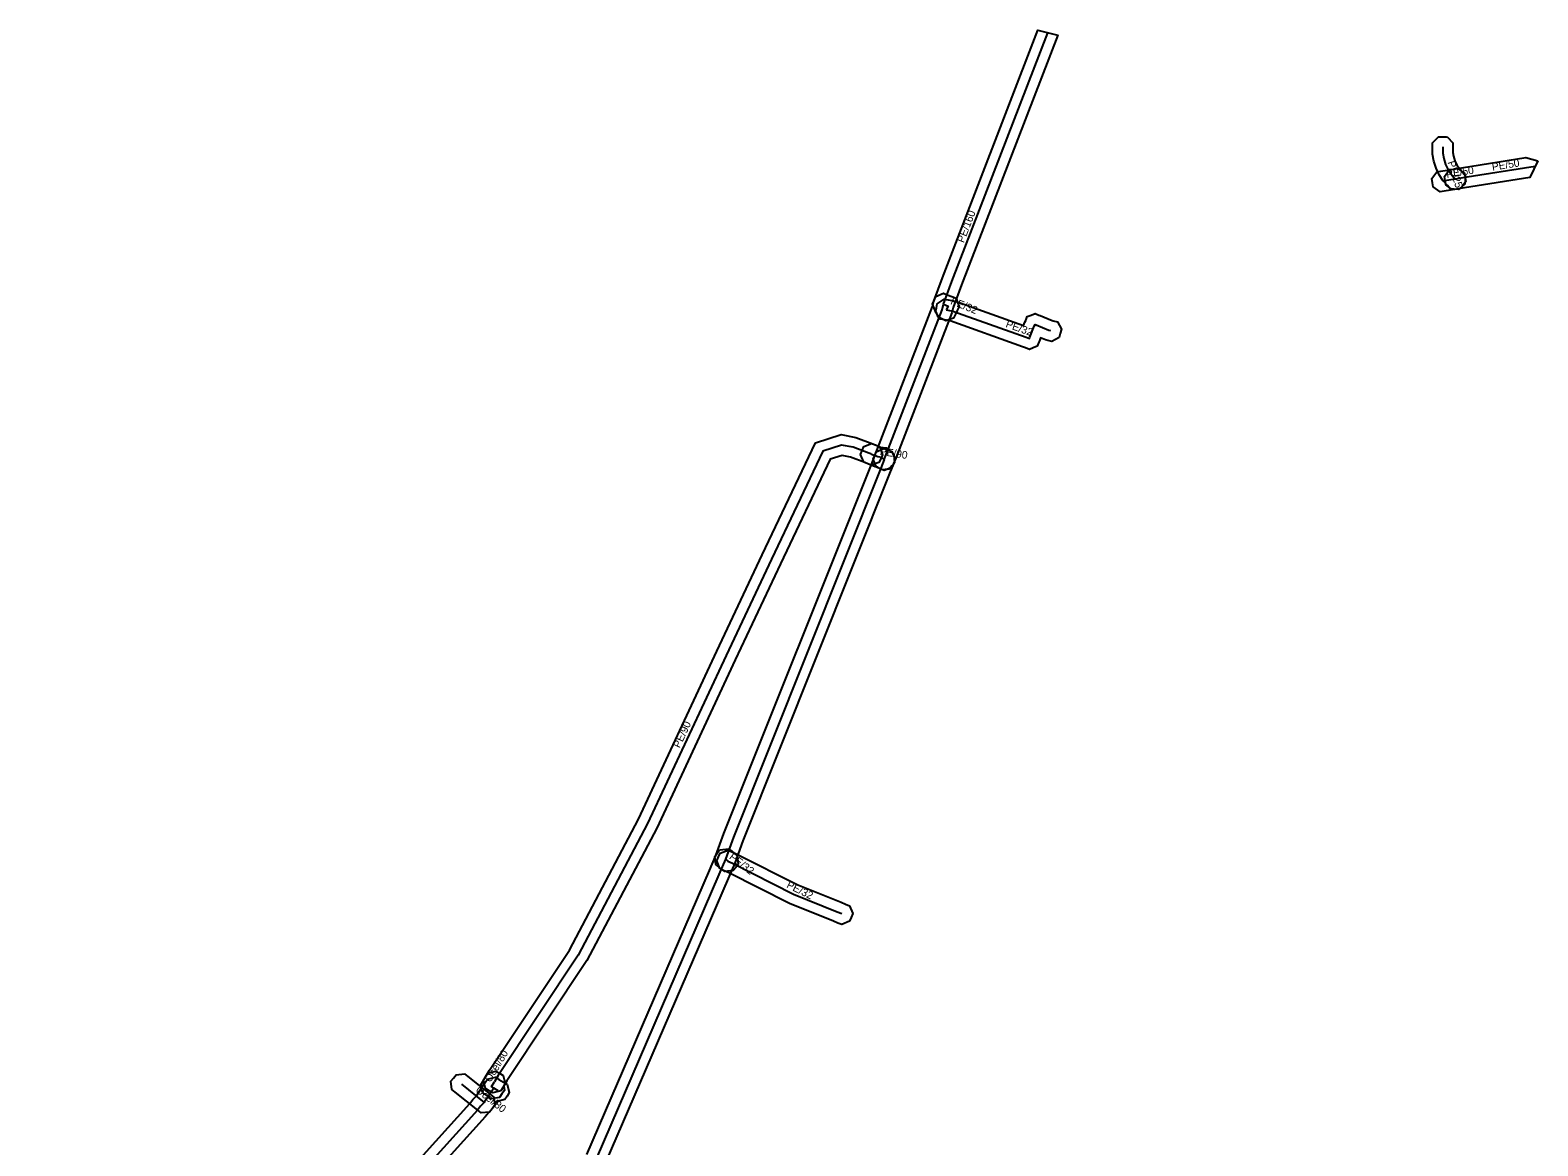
# Model space of a CAD drawing. Extents: x -843502 to -843208, y -997248 to -997028.
# Drawn here: x -843356.7 to -843208.1, y -997138.4 to -997028.5 of the extents above; entities that cross this region are included whole.
import ezdxf

# ---------------------------------------------------------------- set-up
doc = ezdxf.new("R2010")
doc.units = 0
for name, color, linetype in [('1', 7, 'Continuous'), ('24', 7, 'Continuous'), ('30', 7, 'Continuous')]:
    doc.layers.add(name, color=color, linetype=linetype)

msp = doc.modelspace()

# ---------------------------------------------------------------- linework, layer by layer
at = {"layer": '1'}
for points in [[(-843266.81, -997052.89), (-843257.39, -997028.49), (-843255.44, -997029), (-843264.93, -997053.59), (-843265.74, -997055.8), (-843265.89, -997056.34), (-843271.4, -997070.67), (-843271.62, -997071.17), (-843271.78, -997071.56), (-843272.55, -997071.86), (-843272.93, -997071.7), (-843273.31, -997071.54), (-843273.62, -997070.77), (-843273.46, -997070.39), (-843273.26, -997069.91), (-843267.79, -997055.72), (-843267.64, -997055.19)], [(-843217.19, -997038.99), (-843217.06, -997039.02), (-843216.51, -997039.58), (-843216.51, -997039.99), (-843216.51, -997040.54), (-843216.45, -997040.92), (-843216.31, -997041.35), (-843216.12, -997041.76), (-843215.9, -997042.09), (-843215.54, -997042.51), (-843215.27, -997042.83), (-843215.34, -997043.65), (-843215.65, -997043.92), (-843215.97, -997044.19), (-843216.79, -997044.12), (-843217.06, -997043.81), (-843217.5, -997043.29), (-843217.86, -997042.74), (-843218.17, -997042.09), (-843218.39, -997041.39), (-843218.51, -997040.7), (-843218.51, -997039.99), (-843218.51, -997039.58), (-843217.92, -997038.99), (-843217.51, -997038.99)], [(-843215.73, -997044.08), (-843216.14, -997044.15), (-843217.37, -997044.35), (-843217.78, -997044.41), (-843218.45, -997043.93), (-843218.52, -997043.52), (-843218.58, -997043.11), (-843218.1, -997042.44), (-843217.69, -997042.37), (-843216.46, -997042.17), (-843216.05, -997042.11), (-843215.38, -997042.59), (-843215.31, -997043), (-843215.25, -997043.41)], [(-843208.15, -997041.35), (-843208.94, -997043), (-843215.36, -997044.03), (-843216.15, -997044.15), (-843216.56, -997044.21), (-843217.22, -997043.72), (-843217.29, -997043.31), (-843217.35, -997042.9), (-843216.86, -997042.23), (-843216.45, -997042.17), (-843215.68, -997042.05), (-843209.34, -997041.04)], [(-843267.23, -997056.76), (-843267.39, -997056.29), (-843267.45, -997056.26), (-843267.77, -997055.5), (-843267.62, -997055.12), (-843267.46, -997054.73), (-843266.7, -997054.41), (-843266.32, -997054.56), (-843265.87, -997054.74), (-843265.46, -997054.9), (-843265.31, -997055.31), (-843265.15, -997055.72), (-843265.34, -997056.11), (-843265.52, -997056.48), (-843265.7, -997056.85), (-843266.48, -997057.12), (-843266.86, -997056.94)], [(-843265.52, -997055.19), (-843258.8, -997057.59), (-843258.68, -997057.27), (-843258.6, -997057.1), (-843258.45, -997056.71), (-843258.06, -997056.56), (-843257.68, -997056.4), (-843257.3, -997056.56), (-843257.18, -997056.61), (-843256, -997057.09), (-843255.88, -997057.13), (-843255.48, -997057.24), (-843255.08, -997057.96), (-843255.19, -997058.36), (-843255.3, -997058.76), (-843256.02, -997059.17), (-843256.42, -997059.05), (-843256.66, -997058.99), (-843257.13, -997058.79), (-843257.25, -997059.09), (-843257.31, -997059.24), (-843257.47, -997059.63), (-843257.85, -997059.79), (-843258.23, -997059.95), (-843258.62, -997059.8), (-843258.92, -997059.68), (-843266.04, -997057.13), (-843266.6, -997057.02), (-843267.01, -997056.95), (-843267.48, -997056.26), (-843267.4, -997055.86), (-843267.33, -997055.45), (-843266.64, -997054.98), (-843266.24, -997055.06)], [(-843273.84, -997071.36), (-843274.22, -997071.18), (-843274.31, -997071.14), (-843274.44, -997071.07), (-843275.86, -997070.55), (-843276.67, -997070.4), (-843277.85, -997070.77), (-843282.75, -997081.05), (-843287.21, -997090.52), (-843294.94, -997107.09), (-843301.83, -997120.13), (-843309.71, -997131.99), (-843310.08, -997132.61), (-843310.29, -997132.97), (-843311.09, -997133.18), (-843311.45, -997132.97), (-843311.8, -997132.76), (-843312.01, -997131.96), (-843311.8, -997131.6), (-843311.41, -997130.93), (-843303.55, -997119.11), (-843296.74, -997106.21), (-843289.03, -997089.67), (-843284.55, -997080.19), (-843279.29, -997069.13), (-843276.79, -997068.34), (-843275.32, -997068.61), (-843273.66, -997069.23), (-843273.44, -997069.33), (-843273.34, -997069.38), (-843272.97, -997069.56), (-843272.7, -997070.34), (-843272.88, -997070.72), (-843273.06, -997071.09)], [(-843272.86, -997071.82), (-843273.18, -997071.55), (-843273.19, -997071.54), (-843273.44, -997071.5), (-843274.16, -997071.21), (-843274.54, -997071.05), (-843274.86, -997070.28), (-843274.71, -997069.9), (-843274.55, -997069.52), (-843273.78, -997069.2), (-843273.4, -997069.35), (-843272.9, -997069.56), (-843272.35, -997069.64), (-843271.9, -997070.01), (-843271.58, -997070.28), (-843271.51, -997071.1), (-843271.77, -997071.42), (-843272.04, -997071.74)], [(-843287.89, -997109.13), (-843287.56, -997109.38), (-843287.33, -997109.56), (-843287.01, -997109.82), (-843286.91, -997110.64), (-843287.16, -997110.97), (-843287.42, -997111.29), (-843288.24, -997111.39), (-843288.57, -997111.14), (-843288.8, -997110.96), (-843289.12, -997110.7), (-843289.22, -997109.88), (-843288.97, -997109.55), (-843288.71, -997109.23)], [(-843287.91, -997109.27), (-843287.54, -997109.44), (-843287.06, -997109.66), (-843281.05, -997112.69), (-843276.78, -997114.41), (-843276.34, -997114.59), (-843275.96, -997114.75), (-843275.64, -997115.52), (-843275.79, -997115.9), (-843275.95, -997116.28), (-843276.71, -997116.6), (-843277.1, -997116.45), (-843277.54, -997116.27), (-843281.87, -997114.51), (-843287.92, -997111.46), (-843288.36, -997111.26), (-843288.74, -997111.09), (-843289.03, -997110.31), (-843288.86, -997109.94), (-843288.69, -997109.56)], [(-843313.88, -997131.3), (-843313.56, -997131.56), (-843311.32, -997133.34), (-843310.99, -997133.59), (-843310.9, -997134.42), (-843311.16, -997134.74), (-843311.42, -997135.07), (-843312.24, -997135.16), (-843312.56, -997134.9), (-843314.8, -997133.12), (-843315.13, -997132.86), (-843315.22, -997132.04), (-843314.96, -997131.72), (-843314.71, -997131.39)], [(-843309.87, -997132.27), (-843310.02, -997132.52), (-843309.95, -997132.95), (-843310.19, -997133.29), (-843310.43, -997133.63), (-843311.24, -997133.77), (-843311.58, -997133.52), (-843311.79, -997133.37), (-843312.11, -997133.15), (-843312.27, -997132.38), (-843312.07, -997132.05), (-843311.8, -997131.6), (-843311.58, -997131.24), (-843310.78, -997131.04), (-843310.43, -997131.25), (-843310.07, -997131.47)]]:
    msp.add_lwpolyline(points, close=True, dxfattribs=at)
for points in [[(-843301.82, -997139.24), (-843289.74, -997111.29), (-843289.11, -997109.8), (-843288.32, -997107.64), (-843273.8, -997071.29), (-843273.47, -997070.43), (-843273.33, -997070.04), (-843272.57, -997069.7), (-843272.19, -997069.85), (-843271.8, -997069.99), (-843271.46, -997070.75), (-843271.6, -997071.14), (-843271.94, -997072.01), (-843286.46, -997108.36), (-843287.25, -997110.54), (-843287.9, -997112.07), (-843300.02, -997140.1)], [(-843320.04, -997141.66), (-843313.36, -997134.23), (-843313.05, -997133.83), (-843312.7, -997133.47), (-843311.83, -997132.16), (-843311.61, -997131.82), (-843310.83, -997131.65), (-843310.49, -997131.85), (-843310.04, -997132.12), (-843309.68, -997132.34), (-843309.48, -997133.14), (-843309.69, -997133.49), (-843309.91, -997133.85), (-843310.68, -997134.04), (-843311.09, -997134.66), (-843311.19, -997134.78), (-843311.53, -997135.15), (-843311.84, -997135.53), (-843318.54, -997142.98)]]:
    msp.add_lwpolyline(points, dxfattribs=at)
at = {"layer": '24'}
for points in [[(-843272.54, -997070.78), (-843272.33, -997070.29), (-843266.84, -997056.03), (-843266.69, -997055.49), (-843265.87, -997053.24), (-843256.41, -997028.74)], [(-843217.51, -997039.99), (-843217.51, -997040.62), (-843217.42, -997041.15), (-843217.24, -997041.72), (-843216.99, -997042.25), (-843216.7, -997042.69), (-843216.3, -997043.16)], [(-843208.41, -997041.91), (-843215.52, -997043.04), (-843216.3, -997043.16)], [(-843216.3, -997043.16), (-843217.53, -997043.36)], [(-843266.69, -997055.49), (-843266.24, -997055.67), (-843266.42, -997056.04)], [(-843266.42, -997056.04), (-843265.78, -997056.16), (-843258.56, -997058.74), (-843258.24, -997058.87), (-843258.18, -997058.72), (-843257.75, -997057.65), (-843257.68, -997057.48), (-843257.56, -997057.53), (-843256.33, -997058.04), (-843256.15, -997058.09)], [(-843273.78, -997070.28), (-843273.87, -997070.23), (-843274.05, -997070.15), (-843275.59, -997069.58), (-843276.73, -997069.37), (-843278.57, -997069.95), (-843283.65, -997080.62), (-843288.12, -997090.09), (-843295.84, -997106.65), (-843302.69, -997119.62), (-843310.56, -997131.46), (-843310.94, -997132.11)], [(-843272.54, -997070.78), (-843272.77, -997070.59), (-843273.17, -997070.53), (-843273.78, -997070.28)], [(-843272.54, -997070.78), (-843272.87, -997071.65), (-843287.39, -997108), (-843288.18, -997110.17), (-843288.82, -997111.68), (-843300.92, -997139.67), (-843312.51, -997162.15), (-843312.74, -997162.52), (-843312.91, -997162.93), (-843344.27, -997222.18), (-843344.43, -997222.63), (-843347.06, -997227.45), (-843347.36, -997228.03), (-843356.67, -997247.39)], [(-843288.18, -997110.17), (-843287.95, -997110.35)], [(-843287.95, -997110.35), (-843287.49, -997110.56), (-843281.46, -997113.6), (-843277.16, -997115.34), (-843276.72, -997115.52)], [(-843310.55, -997132.98), (-843311, -997132.71), (-843311.9, -997134.07), (-843311.94, -997134.12), (-843312.29, -997134.49), (-843312.6, -997134.88), (-843319.29, -997142.32), (-843327.05, -997151.29), (-843337.8, -997164.01), (-843343.51, -997170.68), (-843343.66, -997170.87), (-843344.19, -997171.44)], [(-843314.18, -997132.34), (-843311.94, -997134.12)], [(-843311, -997132.71), (-843311.21, -997132.56), (-843310.94, -997132.11)]]:
    msp.add_lwpolyline(points, dxfattribs=at)

# ---------------------------------------------------------------- texts
at = {"layer": '30'}
for s, rotation, p in [('PE/50', 9.2356, (-843217.11, -997043.06)), ('PE/25', 287.5256, (-843217.05, -997041.5)), ('PE/50', 9.0611, (-843212.61, -997042.34)), ('PE/160', 68.8876, (-843264.7, -997049.5)), ('PE/32', 338.1986, (-843266.07, -997055.46)), ('PE/32', 340.3361, (-843260.63, -997057.73)), ('PE/90', 351.4692, (-843273, -997070.33)), ('PE/90', 65.0058, (-843292.69, -997099.27)), ('PE/32', 321.953, (-843287.87, -997110.06)), ('PE/32', 333.2452, (-843282.22, -997112.92)), ('Ocel/80', 59.0362, (-843311.32, -997132.2)), ('Ocel/80', 321.5278, (-843312.86, -997133.03))]:
    msp.add_text(s, height=0.75, rotation=rotation, dxfattribs=at).set_placement(p)

doc.saveas('drawing.dxf')
